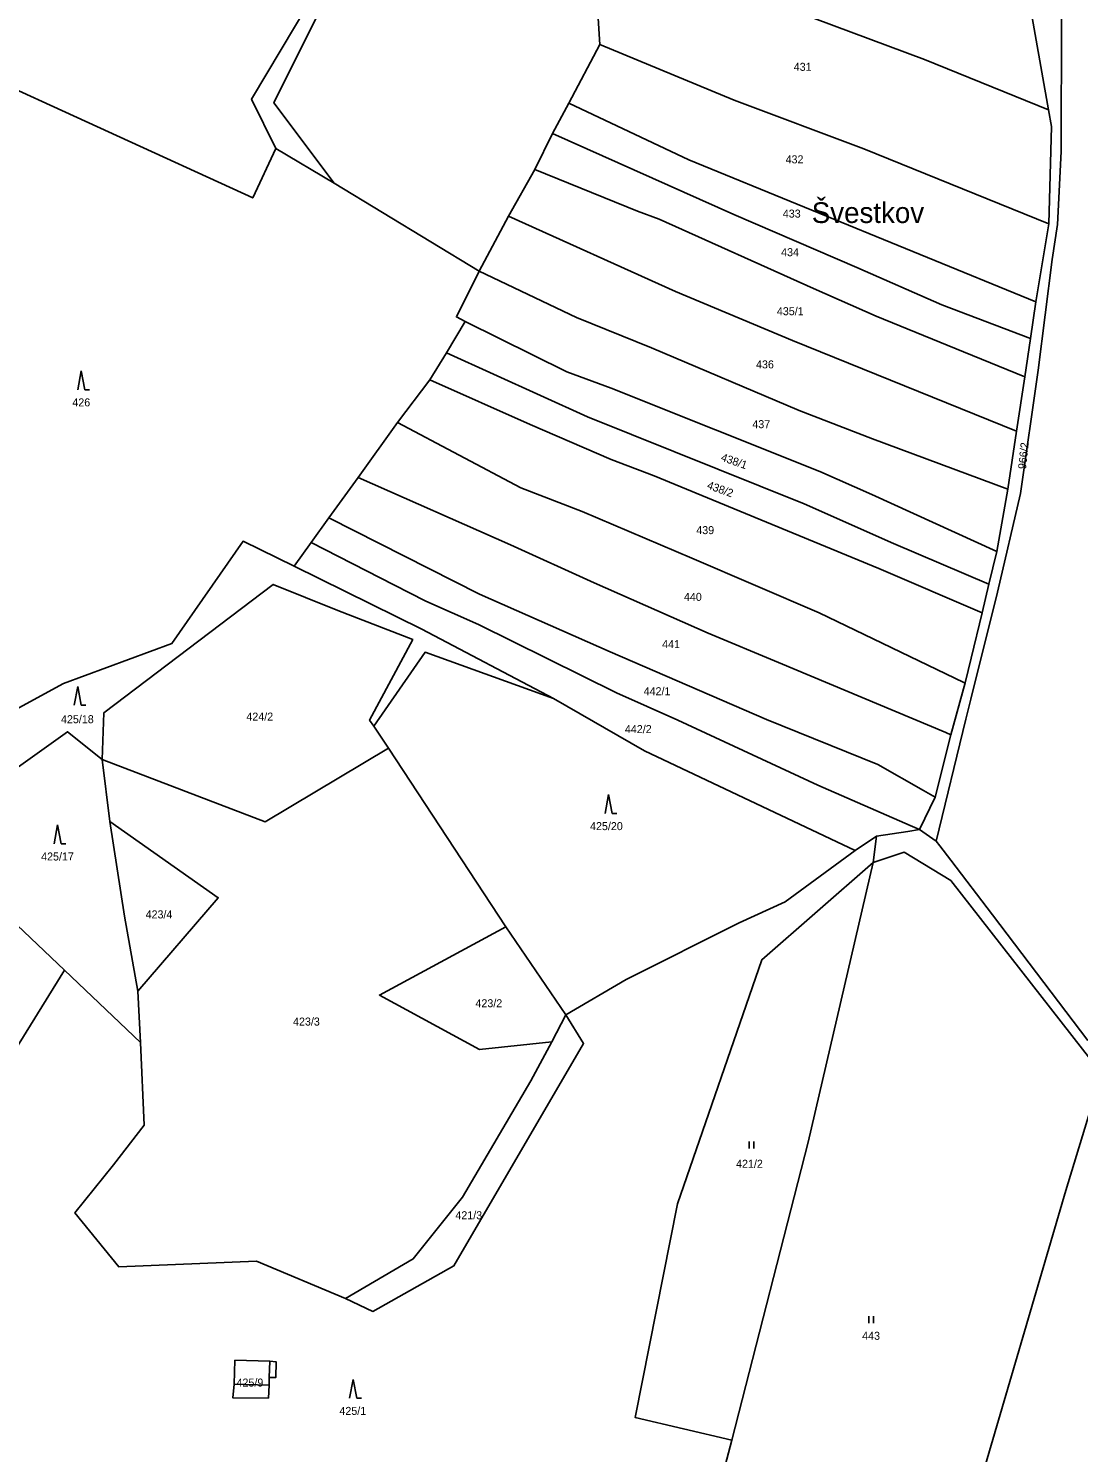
# Model space of a CAD drawing. Extents: x -751333 to -746055, y -1133395 to -1129777.
# Drawn here: x -748676.3 to -748453.3, y -1130426.4 to -1130123.8 of the extents above; entities that cross this region are included whole.
import ezdxf

# ---------------------------------------------------------------- set-up
doc = ezdxf.new("R2010")
doc.units = 0
for name, color, linetype in [('Hranice parcel', 7, 'Continuous'), ('Parcelní čísla', 7, 'Continuous'), ('Pop  PČ popisy', 7, 'Continuous'), ('Vnitřní kresba', 7, 'Continuous'), ('Značky kultur', 7, 'Continuous')]:
    doc.layers.add(name, color=color, linetype=linetype)

msp = doc.modelspace()

# ---------------------------------------------------------------- linework, layer by layer
at = {"layer": 'Hranice parcel'}
for p, q in [((-748466.15, -1130104.47), (-748459.63, -1130141.06)), ((-748561.53, -1130139.64), (-748554.91, -1130127.21)), ((-748564.97, -1130146.11), (-748561.53, -1130139.64)), ((-748568.71, -1130153.77), (-748564.97, -1130146.11)), ((-748611.37, -1130156.66), (-748623.71, -1130149.3)), ((-748574.36, -1130163.67), (-748568.71, -1130153.77)), ((-748611.37, -1130156.66), (-748580.55, -1130175.36)), ((-748580.55, -1130175.36), (-748574.36, -1130163.67)), ((-748459.6, -1130165.33), (-748462.32, -1130181.85)), ((-748462.32, -1130181.85), (-748463.49, -1130189.7)), ((-748587.49, -1130192.68), (-748583.5, -1130186.06)), ((-748463.49, -1130189.7), (-748464.7, -1130197.82)), ((-748591.06, -1130198.48), (-748587.49, -1130192.68)), ((-748464.7, -1130197.82), (-748466.42, -1130209.39)), ((-748597.88, -1130207.54), (-748591.06, -1130198.48)), ((-748606.27, -1130219.19), (-748597.88, -1130207.54)), ((-748466.42, -1130209.39), (-748468.25, -1130221.65)), ((-748612.46, -1130227.78), (-748606.27, -1130219.19)), ((-748468.25, -1130221.65), (-748470.65, -1130234.94)), ((-748616.25, -1130233.04), (-748612.46, -1130227.78)), ((-748619.86, -1130238.05), (-748616.25, -1130233.04)), ((-748470.65, -1130234.94), (-748472.29, -1130241.88)), ((-748472.29, -1130241.88), (-748473.73, -1130247.97)), ((-748477.36, -1130262.85), (-748480.37, -1130273.85)), ((-748599.78, -1130276.68), (-748602.94, -1130272.05)), ((-748574.9, -1130314.67), (-748599.78, -1130276.68)), ((-748480.37, -1130273.85), (-748483.69, -1130287.08)), ((-748660.62, -1130279.14), (-748659.01, -1130292.27)), ((-748483.69, -1130287.08), (-748487.01, -1130294)), ((-748668.63, -1130323.88), (-748698.75, -1130295.21)), ((-748496.14, -1130295.43), (-748500.69, -1130298.48)), ((-748496.89, -1130300.99), (-748496.14, -1130295.43)), ((-748562.18, -1130333.35), (-748574.9, -1130314.67)), ((-748652.52, -1130339.21), (-748668.63, -1130323.88)), ((-748653.04, -1130328.3), (-748652.52, -1130339.21)), ((-748562.18, -1130333.35), (-748565.15, -1130339.08)), ((-748534.52, -1130452.93), (-748526.93, -1130423.75))]:
    msp.add_line(p, q, dxfattribs=at)
for points in [[(-748623.71, -1130149.3), (-748628.91, -1130138.82), (-748616.55, -1130118.04), (-748606.12, -1130088.74), (-748595.25, -1130054.85), (-748593.06, -1130055.51)], [(-748594.69, -1130061.76), (-748602.62, -1130086.59), (-748614.51, -1130120.24), (-748624.15, -1130139.59), (-748611.37, -1130156.66)], [(-748554.91, -1130127.21), (-748555.52, -1130118.22), (-748559.71, -1130102.84)], [(-748459.63, -1130141.06), (-748485.96, -1130130.36), (-748559.71, -1130102.84)], [(-748483.53, -1130296.44), (-748477.18, -1130270.52), (-748476.15, -1130266.32), (-748470.48, -1130243.55), (-748465.59, -1130222.58), (-748461.82, -1130196.42), (-748458.85, -1130172.86), (-748457.7, -1130165.45), (-748456.93, -1130149.91), (-748456.85, -1130121.44), (-748456.83, -1130113.85), (-748458.59, -1130113.78), (-748459.94, -1130113.73), (-748459.91, -1130107.97), (-748459.9, -1130106.56)], [(-748554.91, -1130127.21), (-748526.41, -1130139.04), (-748498.84, -1130149.34), (-748459.6, -1130165.33)], [(-748690.03, -1130131.77), (-748628.64, -1130159.81), (-748623.71, -1130149.3)], [(-748561.53, -1130139.64), (-748536.05, -1130151.71), (-748462.32, -1130181.85)], [(-748459.63, -1130141.06), (-748458.99, -1130144.65), (-748459.6, -1130165.33)], [(-748564.97, -1130146.11), (-748526.49, -1130163.3), (-748500.36, -1130174.61), (-748482.3, -1130182.53), (-748463.49, -1130189.7)], [(-748568.71, -1130153.77), (-748546.93, -1130162.59), (-748542.36, -1130164.35), (-748509.55, -1130179.04), (-748496.23, -1130184.94), (-748477.7, -1130192.53), (-748464.7, -1130197.82)], [(-748574.36, -1130163.67), (-748538.88, -1130179.65), (-748514.01, -1130190.06), (-748466.42, -1130209.39)], [(-748583.5, -1130186.06), (-748585.39, -1130185.07), (-748580.55, -1130175.36)], [(-748580.55, -1130175.36), (-748559.9, -1130185.18), (-748543.93, -1130191.62), (-748512.59, -1130205), (-748497.05, -1130211.01), (-748468.25, -1130221.65)], [(-748583.5, -1130186.06), (-748561.91, -1130196.77), (-748552.49, -1130200.2), (-748508.22, -1130217.94), (-748497.13, -1130222.78), (-748470.65, -1130234.94)], [(-748587.49, -1130192.68), (-748557.54, -1130206.34), (-748511.54, -1130224.78), (-748492.59, -1130233.23), (-748472.29, -1130241.88)], [(-748591.06, -1130198.48), (-748569.76, -1130207.93), (-748552.49, -1130215.39), (-748543.4, -1130218.84), (-748495.65, -1130238.56), (-748473.73, -1130247.97)], [(-748597.88, -1130207.54), (-748571.74, -1130221.42), (-748558.68, -1130226.43), (-748535.42, -1130236.35), (-748508.36, -1130247.92), (-748477.63, -1130262.72), (-748477.36, -1130262.85)], [(-748606.27, -1130219.19), (-748573.91, -1130233.52), (-748556.1, -1130241.56), (-748531.92, -1130252.3), (-748516.99, -1130258.52), (-748481.48, -1130273.38), (-748480.37, -1130273.85)], [(-748612.46, -1130227.78), (-748580.46, -1130243.96), (-748552.74, -1130256.21), (-748519.52, -1130270.64), (-748495.86, -1130280.16), (-748486.17, -1130285.67), (-748483.69, -1130287.08)], [(-748619.86, -1130238.05), (-748630.7, -1130232.75), (-748645.83, -1130254.45), (-748668.82, -1130263), (-748689.45, -1130274.13), (-748701.54, -1130278.1), (-748711.73, -1130280.94), (-748727.3, -1130286.44), (-748738.44, -1130293.13)], [(-748616.25, -1130233.04), (-748598.71, -1130241.97), (-748591.86, -1130245.5), (-748580.73, -1130250.44), (-748551.39, -1130264.93), (-748538.39, -1130270.74), (-748508.62, -1130284.54), (-748489.01, -1130293.13), (-748487.01, -1130294)], [(-748564.77, -1130266.14), (-748592.71, -1130251.42), (-748619.86, -1130238.05)], [(-748602.94, -1130272.05), (-748603.83, -1130270.75), (-748594.68, -1130253.65), (-748610.6, -1130247.49), (-748624.3, -1130241.91), (-748660.24, -1130269.18), (-748660.62, -1130279.14)], [(-748473.73, -1130247.97), (-748476.08, -1130257.59), (-748477.36, -1130262.85)], [(-748602.94, -1130272.05), (-748592.05, -1130256.31), (-748564.77, -1130266.14)], [(-748500.69, -1130298.48), (-748545.44, -1130277.27), (-748564.77, -1130266.14)], [(-748660.62, -1130279.14), (-748667.98, -1130273.2), (-748698.75, -1130295.21)], [(-748599.78, -1130276.68), (-748625.99, -1130292.35), (-748660.62, -1130279.14)], [(-748659.01, -1130292.27), (-748635.99, -1130308.5), (-748653.04, -1130328.3)], [(-748659.01, -1130292.27), (-748655.88, -1130312.42), (-748653.04, -1130328.3)], [(-748487.01, -1130294), (-748489.49, -1130294.39), (-748496.14, -1130295.43)], [(-748483.53, -1130296.44), (-748486.31, -1130294.49), (-748487.01, -1130294)], [(-748451.27, -1130338.82), (-748471.54, -1130312.1), (-748480.37, -1130300.47), (-748482.72, -1130297.47), (-748483.53, -1130296.44)], [(-748500.69, -1130298.48), (-748515.57, -1130309.37), (-748525.37, -1130313.83), (-748549.31, -1130325.87), (-748562.18, -1130333.35)], [(-748496.89, -1130300.99), (-748490.31, -1130298.81), (-748480.41, -1130304.83), (-748448.4, -1130345.8)], [(-748496.89, -1130300.99), (-748520.5, -1130321.67), (-748538.42, -1130373.55), (-748547.42, -1130418.91), (-748526.93, -1130423.75)], [(-748526.93, -1130423.75), (-748510.69, -1130360.38), (-748496.89, -1130300.99)], [(-748574.9, -1130314.67), (-748601.75, -1130329.18), (-748580.46, -1130340.74), (-748565.15, -1130339.08)], [(-748668.63, -1130323.88), (-748723.49, -1130412.55), (-748757.6, -1130467.05)], [(-748608.98, -1130393.62), (-748603.14, -1130396.37), (-748585.91, -1130386.69), (-748558.39, -1130339.43), (-748562.18, -1130333.35)], [(-748652.52, -1130339.21), (-748651.69, -1130356.8), (-748658.21, -1130365.26), (-748666.43, -1130375.43), (-748657.09, -1130386.87), (-748627.84, -1130385.7), (-748608.98, -1130393.62)], [(-748565.15, -1130339.08), (-748569.6, -1130347.41), (-748584.08, -1130372.07), (-748594.55, -1130385.22), (-748608.98, -1130393.62)], [(-748491.6, -1130492.22), (-748475.41, -1130437.09), (-748455.96, -1130370.65), (-748448.4, -1130345.8)], [(-748625.33, -1130414.81), (-748625.17, -1130412.04), (-748625.14, -1130410.38), (-748623.76, -1130410.44), (-748623.68, -1130407.06), (-748625.04, -1130406.97), (-748632.45, -1130406.76), (-748632.61, -1130411.83), (-748632.87, -1130414.74), (-748625.33, -1130414.81)]]:
    msp.add_lwpolyline(points, dxfattribs=at)
at = {"layer": 'Vnitřní kresba'}
for p, q in [((-748625.14, -1130410.38), (-748625.04, -1130406.97)), ((-748632.61, -1130411.83), (-748625.17, -1130412.04))]:
    msp.add_line(p, q, dxfattribs=at)
at = {"layer": 'Značky kultur'}
for p, q in [((-748665.07, -1130196.54), (-748665.82, -1130200.54)), ((-748664.32, -1130200.54), (-748665.07, -1130196.54)), ((-748664.32, -1130200.54), (-748663.324, -1130200.54)), ((-748665.82, -1130263.59), (-748666.57, -1130267.59)), ((-748665.07, -1130267.59), (-748665.82, -1130263.59)), ((-748665.07, -1130267.59), (-748664.074, -1130267.59)), ((-748553.08, -1130286.57), (-748553.83, -1130290.57)), ((-748552.33, -1130290.57), (-748553.08, -1130286.57)), ((-748552.33, -1130290.57), (-748551.334, -1130290.57)), ((-748670.09, -1130293.02), (-748670.84, -1130297.02)), ((-748669.34, -1130297.02), (-748670.09, -1130293.02)), ((-748669.34, -1130297.02), (-748668.344, -1130297.02)), ((-748523.241, -1130361.74), (-748523.241, -1130360.24)), ((-748522.24, -1130361.74), (-748522.24, -1130360.24)), ((-748497.831, -1130398.85), (-748497.831, -1130397.35)), ((-748496.83, -1130398.85), (-748496.83, -1130397.35)), ((-748607.32, -1130410.81), (-748608.07, -1130414.81)), ((-748606.57, -1130414.81), (-748607.32, -1130410.81)), ((-748606.57, -1130414.81), (-748605.574, -1130414.81))]:
    msp.add_line(p, q, dxfattribs=at)

# ---------------------------------------------------------------- texts
at = {"layer": 'Parcelní čísla'}
for s, p in [('431', (-748513.75, -1130132.8)), ('432', (-748515.48, -1130152.46)), ('433', (-748516.07, -1130163.98)), ('434', (-748516.43, -1130172.18)), ('435/1', (-748517.33, -1130184.72)), ('436', (-748521.76, -1130196.02)), ('426', (-748666.96, -1130204.09)), ('437', (-748522.54, -1130208.72)), ('439', (-748534.45, -1130231.23)), ('440', (-748537.07, -1130245.41)), ('441', (-748541.7, -1130255.45)), ('442/1', (-748545.63, -1130265.46)), ('425/18', (-748669.37, -1130271.4)), ('424/2', (-748630, -1130270.85)), ('442/2', (-748549.61, -1130273.5)), ('425/20', (-748557.01, -1130294.12)), ('425/17', (-748673.59, -1130300.57)), ('423/4', (-748651.4, -1130312.87)), ('423/2', (-748581.35, -1130331.75)), ('423/3', (-748620.09, -1130335.64)), ('421/2', (-748526, -1130365.85)), ('421/3', (-748585.61, -1130376.79)), ('443', (-748499.22, -1130402.4)), ('425/9', (-748632.09, -1130412.34)), ('425/1', (-748610.24, -1130418.36))]:
    msp.add_text(s, height=1.7, dxfattribs=at).set_placement(p)
for s, rotation, p in [('966/2', 84, (-748464.434, -1130217.498)), ('438/1', 341, (-748529.356, -1130215.593)), ('438/2', 340, (-748532.31, -1130221.498))]:
    msp.add_text(s, height=1.7, rotation=rotation, dxfattribs=at).set_placement(p)
at = {"layer": 'Pop  PČ popisy'}
msp.add_text('Švestkov', height=4.4, dxfattribs=at).set_placement((-748509.926, -1130165.13))

doc.saveas('drawing.dxf')
